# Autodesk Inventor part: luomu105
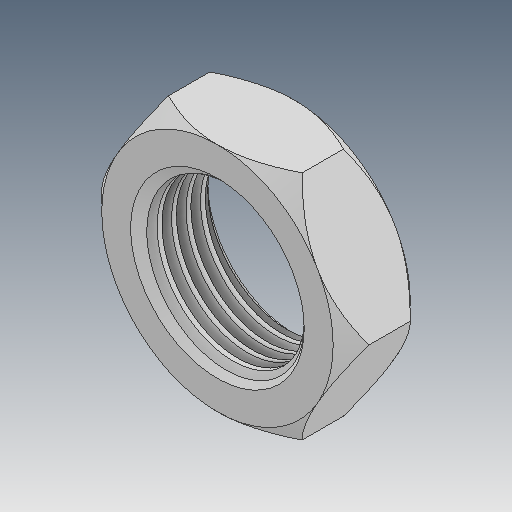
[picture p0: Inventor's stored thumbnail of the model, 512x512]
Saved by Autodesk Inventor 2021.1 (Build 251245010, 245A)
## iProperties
Created: 2018-07
Part Number: luomu105
Material: Ogólny
Document SubType Name: Modeling
Designer: user
Density: 1 g/cm^3
Appearance: Domyślna
Author: user
Revision Number: ÈÎºÎ
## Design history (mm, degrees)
feature "ÇÐ³ý-É¨Ãè1"
node "Bryła1"
